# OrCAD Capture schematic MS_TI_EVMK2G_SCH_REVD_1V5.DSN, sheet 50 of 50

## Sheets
50 49. DC IN, 5V & DDR POWER GEN: size C; title: DDR3L POWER
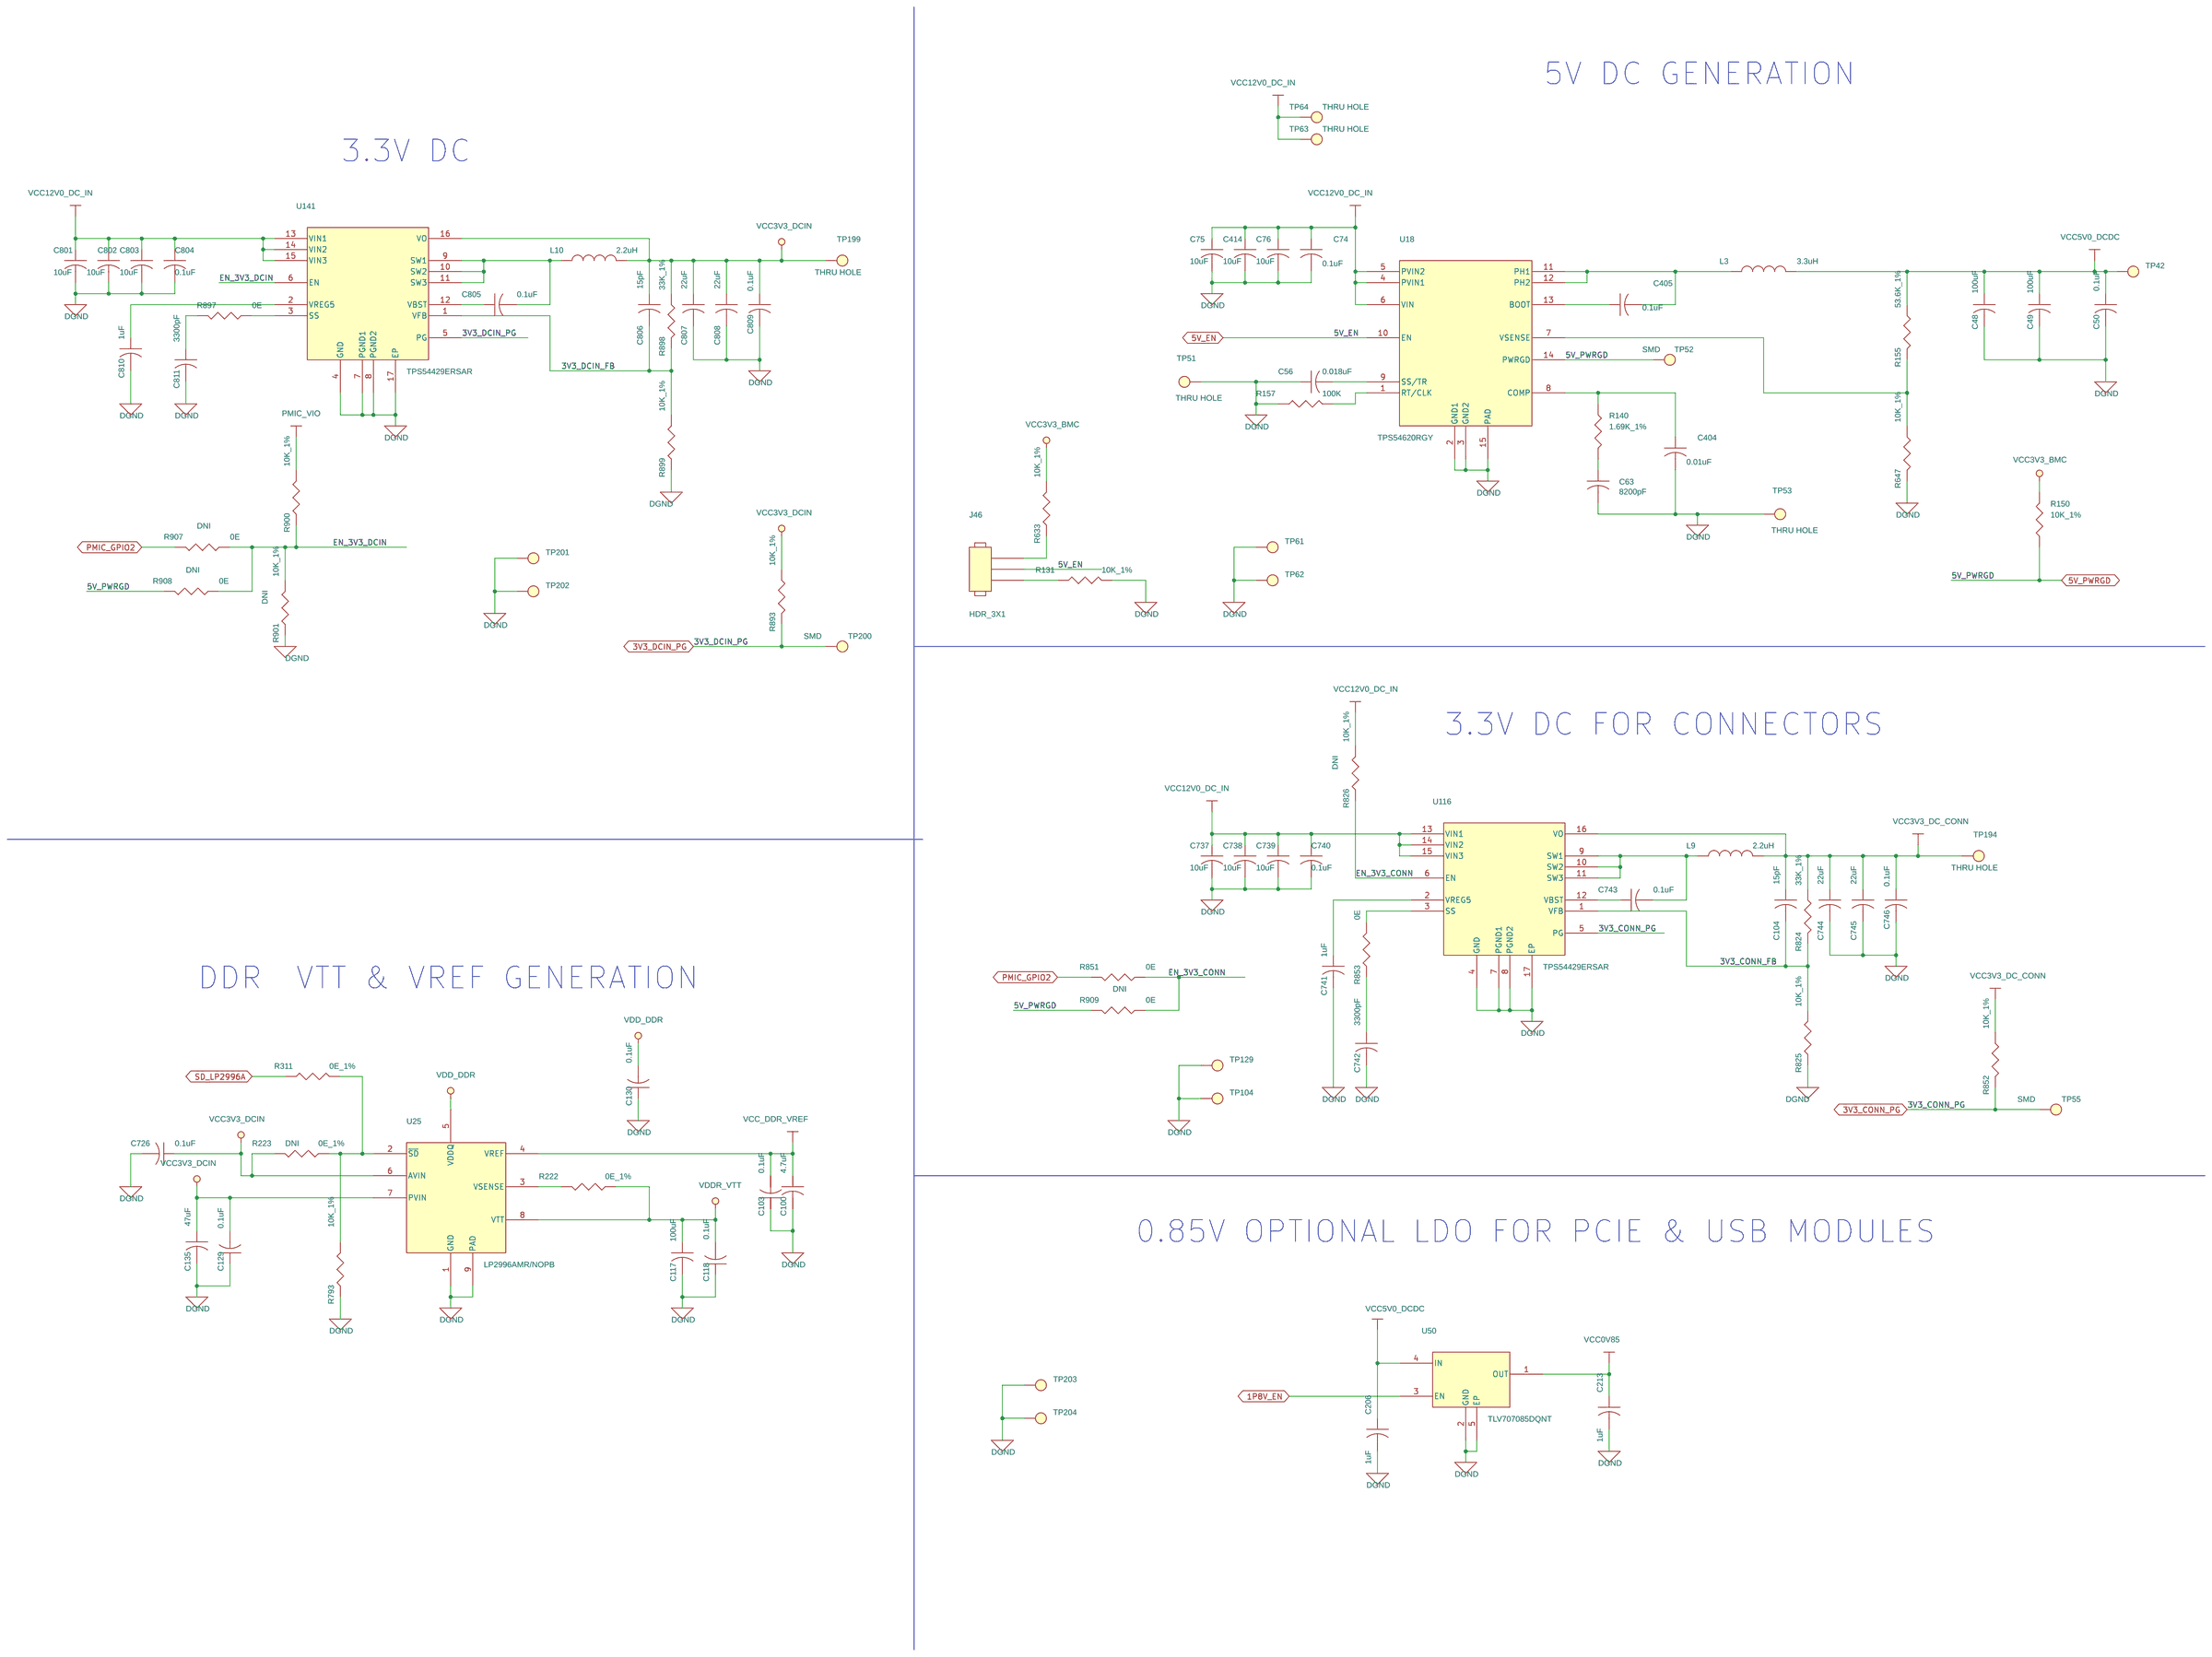
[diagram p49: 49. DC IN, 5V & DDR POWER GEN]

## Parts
C48  100uF  [CAP1210]
C49  100uF  [CAP1210]
C50  0.1uF  [CAP0402]
C56  0.018uF  [CAP0402]
C63  8200pF  [CAP0402]
C74  0.1uF  [CAP0402]
C75  10uF  [CAP1210]
C76  10uF  [CAP1210]
C100  4.7uF  [CAP0603]
C103  0.1uF  [CAP0402]
C104  15pF  [CAP0402]
C117  100uF  [CAP1210]
C118  0.1uF  [CAP0402]
C129  0.1uF  [CAP0402]
C130  0.1uF  [CAP0402]
C135  47uF  [CAP1206]
C206  1uF  [CAP0402]
C213  1uF  [CAP0402]
C404  0.01uF  [CAP0402]
C405  0.1uF  [CAP0402]
C414  10uF  [CAP1210]
C726  0.1uF  [CAP0402]
C737  10uF  [CAP1210]
C738  10uF  [CAP1210]
C739  10uF  [CAP1210]
C740  0.1uF  [CAP0402]
C741  1uF  [CAP0402]
C742  3300pF  [CAP0805]
C743  0.1uF  [CAP0402]
C744  22uF  [CAP1210]
C745  22uF  [CAP1210]
C746  0.1uF  [CAP0402]
C801  10uF  [CAP1210]
C802  10uF  [CAP1210]
C803  10uF  [CAP1210]
C804  0.1uF  [CAP0402]
C805  0.1uF  [CAP0402]
C806  15pF  [CAP0402]
C807  22uF  [CAP1210]
C808  22uF  [CAP1210]
C809  0.1uF  [CAP0402]
C810  1uF  [CAP0402]
C811  3300pF  [CAP0805]
J46  HDR_3X1  [HDR_3X1_100_S_T]
L3  3.3uH  [IND_PCMB104T_455X405_SMD]
L9  2.2uH  [IND_B82476A_510X370_SMD]
L10  2.2uH  [IND_B82476A_510X370_SMD]
R131  10K_1%  [RES0402]
R140  1.69K_1%  [RES0402]
R150  10K_1%  [RES0402]
R155  53.6K_1%  [RES0603]
R157  100K  [RES0402]
R222  0E_1%  [RES0402]
R223  0E_1%  [RES0402]
R311  0E_1%  [RES0402]
R633  10K_1%  [RES0402]
R647  10K_1%  [RES0402]
R793  10K_1%  [RES0402]
R824  33K_1%  [RES0603]
R825  10K_1%  [RES0402]
R826  10K_1%  [RES0402]
R851  0E  [RES0402]
R852  10K_1%  [RES0402]
R853  0E  [RES0402]
R893  10K_1%  [RES0402]
R897  0E  [RES0402]
R898  33K_1%  [RES0603]
R899  10K_1%  [RES0402]
R900  10K_1%  [RES0402]
R901  10K_1%  [RES0402]
R907  0E  [RES0402]
R908  0E  [RES0402]
R909  0E  [RES0402]
TP42  THRU HOLE  [TP_40X65]
TP51  THRU HOLE  [TP_40X65]
TP52  SMD  [TP40_SMD]
TP53  THRU HOLE  [TP_40X65]
TP55  SMD  [TP40_SMD]
TP61  THRU HOLE  [TP_40X65]
TP62  THRU HOLE  [TP_40X65]
TP63  THRU HOLE  [TP_40X65]
TP64  THRU HOLE  [TP_40X65]
TP104  THRU HOLE  [TP_40X65]
TP129  THRU HOLE  [TP_40X65]
TP194  THRU HOLE  [TP_40X65]
TP199  THRU HOLE  [TP_40X65]
TP200  SMD  [TP40_SMD]
TP201  THRU HOLE  [TP_40X65]
TP202  THRU HOLE  [TP_40X65]
TP203  THRU HOLE  [TP_40X65]
TP204  THRU HOLE  [TP_40X65]
U18  TPS54620RGY  [QFN14_19-68_145X145]
U25  LP2996AMR/NOPB  [ESOIC8]
U50  TLV707085DQNT  [DQN_25-59_40X40]
U116  TPS54429ERSAR  [QFN16_25-59_160X160]
U141  TPS54429ERSAR  [QFN16_25-59_160X160]

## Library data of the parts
C48 C49 C117 = CAP: CAP CERAMIC 100uF10V 20% X5R 1210; Chkd/date: MAZHAR/161208; Crtd /date: MAZHAR/140505; Custom_Duty: 15%; Customs_HS_Code: 85322990; Distributor_name: DIGIKEY; Distributor_part_number: 587-1965-1-ND; Height: 2.10MM; Mfr_name: TAIYO YUDEN; Mfr_part_number: LMK325BJ107MM-T; Mistral Part No: 120009030172; Package: 1210; Part_type: CAPACITORS\CERAMIC; Project: SMART VIEW_NVR; Tolerance: 20%; Voltage: 10V; Datasheet: Y:\MIS_DATABASE\DATASHEETS\CAPACITORS\JMKSERIES.PDF
C50 C405 C743 C746 C805 C809 = CAP: CAP CERAMIC 0.1uF 16V 10% X7R 0402; Alternate_mfr_name_A: KEMET; Alternate_mfr_part_number_A: C0402C104K4RACT; Chkd/date: MAZHAR/281108; Crtd /date: MAZHAR/030907; Custom_Duty: 15%; Customs_HS_Code: 85322990; Distributor_name: DIGIKEY; Distributor_name_A: DIGIKEY; Distributor_part_number: 490-3261-1-ND; Distributor_part_number_A: 399-3521-1-ND; Height: 0.55MM; Mfr_name: MURATA; Mfr_part_number: GRM155R71C104KA88D; Mistral Part No: 120009030060-R; Package: 0402; Part_type: CAPACITORS\CERAMIC; Project: SMART VIEW_IP CAMERA; Tolerance: 10%; Voltage: 16V; Datasheet: Y:\MIS_DATABASE\DATASHEETS\CAPACITORS\GRM188SERIES.PDF
C56 = CAP: CAP CERAMIC 0.018uF 16V 10% X7R 0402; Alternate_mfr_name_A: AVX CORPORATION; Alternate_mfr_name_B: MURATA; Alternate_mfr_part_number_A: 0402YC183KAT2A; Alternate_mfr_part_number_B: GRM155R71C183KA01D; Chkd/date: NAVEED/241114; Crtd /date: MUDDU/080310; Custom_Duty: 15%; Customs_HS_Code: 85322990; Distributor_name: DIGIKEY; Distributor_name_A: DIGIKEY; Distributor_name_B: DIGIKEY; Distributor_part_number: PCC2137CT-ND; Distributor_part_number_A: 478-1117-1-ND; Distributor_part_number_B: 490-5417-1-ND; Height: 0.55MM; Mfr_name: PANASONIC-ECG; Mfr_part_number: ECJ-0EB1C183K; Mistral Part No: 120010030006-R; Package: 0402; Part_type: CAPACITORS\CERAMIC; Project: VME_DSP_SUITE; RoHS: RoHS; Temperature: -55°C+125°C; Tolerance: 10%; Voltage: 16V; Wattage: NA; Weight: NA; Datasheet: Y:\MIS_DATABASE\DATASHEETS\CAPACITORS\PAN-ECJ.PDF
C63 = CAP: CAP CERAMIC 8200pf 16V 10% X7R 0402; Chkd/date: MAZHAR/241208; Crtd /date: USMAN/080908; Custom_Duty: 15%; Customs_HS_Code: 85322990; Distributor_name: DIGIKEY; Distributor_part_number: 399-1037-1-ND; Height: 0.55MM; Mfr_name: KEMET; Mfr_part_number: C0402C822K4RACTU; Mistral Part No: 120009030502-R; Package: 0402; Part_type: CAPACITORS\CERAMIC; Project: MDI; RoHS: RoHS; Tolerance: 10%; Voltage: 16V; Datasheet: Y:\MIS_DATABASE\DATASHEETS\CAPACITORS\KEMET-C08.PDF
C74 C103 C118 C129 C130 C726 C740 C804 = CAP: CAP CERAMIC 0.1uF 50V 10% X7R 0402; Alternate_mfr_name_A: TDK CORPORATION; Alternate_mfr_part_number_A: CGA2B3X7R1H104K; Chkd/date: BAVISH/081111; Crtd /date: CHAITHANYA/051011; Custom_Duty: 15%; Customs_HS_Code: 85322990; Distributor_name: DIGIKEY; Distributor_name_A: DIGIKEY; Distributor_part_number: 445-5932-1-ND; Distributor_part_number_A: 445-6899-1-ND; Height: 0.55MM; Mfr_name: TDK CORPORATION; Mfr_part_number: C1005X7R1H104K; Mistral Part No: 120011100014-R; Package: 0402; Part_type: CAPACITORS\CERAMIC; Project: VP-4000-BASE-BOARD; RoHS: RoHS; Temperature: -55°C+125°C; Tolerance: 10%; Voltage: 50V; Wattage: NA; Weight: NA; Datasheet: Y:\MIS_DATABASE\DATASHEETS\CAPACITORS\C1005X7.PDF
C75 C76 C414 C737-C739 C801-C803 = CAP: CAP CERAMIC 10uF 25V 20% X7R 1210; Chkd/date: SHREESHAIL/200707; Crtd /date: MAZHAR/180707; Custom_Duty: 15%; Customs_HS_Code: 85322990; Distributor_name: DIGIKEY; Distributor_part_number: 445-1434-1-ND; Height: 2.80MM; Mfr_name: TDK CORPORATION; Mfr_part_number: C3225X7R1E106M; Mistral Part No: 120009030191-R; Package: 1210; Part_type: CAPACITORS\CERAMIC; Project: REVA-IBMS; RoHS: RoHS; Tolerance: 20%; Voltage: 25V; Datasheet: Y:\MIS_DATABASE\DATASHEETS\CAPACITORS\TDK_CAP.PDF
C100 = CAP: CAP CERAMIC 4.7uF 16V 10% X5R 0603; Chkd/date: VASANTHA/230714; Crtd /date: BAVISH/060511; Custom_Duty: 15%; Customs_HS_Code: 85322990; Distributor_name: DIGIKEY; Distributor_part_number: 587-2786-1-ND; Height: 0.90MM; Mfr_name: TAIYO YUDEN; Mfr_part_number: EMK107ABJ475KA-T; Mistral Part No: 120011050004-R; Package: 0603; Part_type: CAPACITORS\CERAMIC; Project: HMC; RoHS: RoHS; Temperature: -55°C+85°C; Tolerance: 10%; Voltage: 16V; Wattage: NA; Weight: NA; Datasheet: Y:\MIS_DATABASE\DATASHEETS\CAPACITORS\EMK107.PDF
C104 C806 = CAP: CAP CERAMIC 15pF 50V 5% NP0 0402; Alternate_mfr_name_A: AVX CORPORATION; Alternate_mfr_name_B: KEMET; Alternate_mfr_name_D: MURATA; Alternate_mfr_part_number_A: 04025A150JAT2A; Alternate_mfr_part_number_B: C0402C150J5GACTU; Alternate_mfr_part_number_D: GRM1555C1H150JZ01D; Chkd/date: SHREESHAIL/220506; Crtd /date: MAZHAR/150506; Custom_Duty: 15%; Customs_HS_Code: 85322990; Distributor_name: DIGIKEY; Distributor_name_A: DIGIKEY; Distributor_name_B: DIGIKEY; Distributor_name_D: DIGIKEY; Distributor_part_number: PCC150CQCT-ND; Distributor_part_number_A: 478-1072-1-ND; Distributor_part_number_B: 399-1014-1-ND; Distributor_part_number_D: 490-1280-1-ND; Height: 0.55MM; Mfr_name: PANASONIC-ECG; Mfr_part_number: ECJ-0EC1H150J; Mistral Part No: 120009030233-R; Package: 0402; Part_type: CAPACITORS\CERAMIC; Project: VOCERA; RoHS: RoHS; Tolerance: 5%; Voltage: 50V; Datasheet: Y:\MIS_DATABASE\DATASHEETS\CAPACITORS\ECJ.PDF
C135 = CAP: CAP CERAMIC 47uF 16V 20% X5R 1206; Chkd/date: JAGADEESWARAN.S/250414; Crtd /date: BAVISH/010611; Custom_Duty: 15%; Customs_HS_Code: 85322990; Distributor_name: DIGIKEY; Distributor_part_number: 445-6003-1-ND; Height: 1.80MM; Mfr_name: TDK CORPORATION; Mfr_part_number: C3216X5R1C476M; Mistral Part No: 120011060001-R; Package: 1206; Part_type: CAPACITORS\CERAMIC; Project: TE_MODULE; RoHS: RoHS; Temperature: -55°C+85°C; Tolerance: 20%; Voltage: 16V; Wattage: NA; Weight: NA; Datasheet: Y:\MIS_DATABASE\DATASHEETS\CAPACITORS\TDK-C3216.PDF
C206 C213 C741 C810 = CAP: CAP CERAMIC 1uF 10V 10% X5R 0402; Chkd/date: BALACHANDAR/160514; Crtd /date: SARANYA/060514; Custom_Duty: 15%; Customs_HS_Code: 85322990; Distributor_name: DIGIKEY; Distributor_part_number: 478-4596-1-ND; Height: 0.56MM; Mfr_name: AVX CORPORATION; Mfr_part_number: 0402ZD105KAT2A; Mistral Part No: 120014050010-R; Package: 0402; Part_type: CAPACITORS\CERAMIC; Project: AEGIS GP BETA2; RoHS: RoHS; Temperature: -55°C+85°C; Tolerance: 10%; Voltage: 10V; Wattage: NA; Weight: NA; Datasheet: Y:\MIS_DATABASE\DATASHEETS\CAPACITORS\AVX_MLC.PDF
C404 = CAP: CAP CERAMIC 0.01uF 16V 10% X7R 0402; Alternate_mfr_name_A: AVX CORPORATION; Alternate_mfr_name_B: KEMET; Alternate_mfr_name_D: TDK CORPORATION; Alternate_mfr_part_number_A: 0402YC103KAT2A; Alternate_mfr_part_number_B: C0402C103K4RACTU; Alternate_mfr_part_number_D: C1005X7R1C103K; Chkd/date: SHREESHAIL/180506; Crtd /date: MAZHAR/110506; Custom_Duty: 15%; Customs_HS_Code: 85322990; Distributor_name: DIGIKEY; Distributor_name_A: DIGIKEY; Distributor_name_B: DIGIKEY; Distributor_name_D: DIGIKEY; Distributor_part_number: PCC103BQCT-ND; Distributor_part_number_A: 478-1114-1-ND; Distributor_part_number_B: 399-1038-1-ND; Distributor_part_number_D: 445-1262-1-ND; Height: 0.55MM; Mfr_name: PANASONIC-ECG; Mfr_part_number: ECJ-0EB1C103K; Mistral Part No: 120009030032-R; Package: 0402; Part_type: CAPACITORS\CERAMIC; Project: VOCERA; RoHS: RoHS; Tolerance: 10%; Voltage: 16V; Datasheet: Y:\MIS_DATABASE\DATASHEETS\CAPACITORS\PAN-ECJ.PDF
C742 C811 = CAP: CAP CERAMIC 3300pF 50V 5% X7R 0805; Chkd/date: PRASHANTHA/191011; Crtd /date: CHAITHANYA/041011; Custom_Duty: 15%; Customs_HS_Code: 85322990; Distributor_name: MOUSER; Distributor_part_number: 81-GRM216R71H332JA01D; Height: 1.35MM; Mfr_name: MURATA; Mfr_part_number: GRM216R71H332JA01D; Mistral Part No: 120011100005-R; Package: 0805; Part_type: CAPACITORS\CERAMIC; Project: VP-4000-BASE-BOARD; RoHS: RoHS; Temperature: -55°C+125°C; Tolerance: 5%; Voltage: 50V; Wattage: NA; Weight: NA; Datasheet: Y:\MIS_DATABASE\DATASHEETS\CAPACITORS\GRM188SERIES.PDF
C744 C745 C807 C808 = CAP: CAP CERAMIC 22uF 25V 10% X7R 1210; Chkd/date: BAVISH/040311; Crtd /date: MAZHAR/190111; Custom_Duty: 15%; Customs_HS_Code: 85322990; Distributor_name: DIGIKEY; Distributor_part_number: 490-5313-1-ND; Height: 2.70MM; Mfr_name: MURATA; Mfr_part_number: GRM32ER71E226KE15L; Mistral Part No: 120011010016-R; Package: 1210; Part_type: CAPACITORS\CERAMIC; Project: ITS-PWR_CARD; RoHS: RoHS; Temperature: -55°C+125°C; Tolerance: 10%; Voltage: 25V; Wattage: NA; Weight: NA; Datasheet: Y:\MIS_DATABASE\DATASHEETS\CAPACITORS\GRM32,43,55.PDF
J46 = HEADER_3X1: CON HDR 3X1 2.54MM PITCH ST TH; Chkd/date: MAZHAR/100311; Crtd /date: BAVISH/160211; Custom_Duty: 24%; Customs_HS_Code: 85369090; Distributor_name: DIGIKEY; Distributor_part_number: A26545-ND; Height: 10.74MM; Mfr_name: TYCO ELECTRONICS; Mfr_part_number: 87224-3; Mistral Part No: 150011020004-R; Package: THRU-HOLE; Part_type: CONNECTOR\HEADERS; Project: OMAPL1_PEC20; RoHS: RoHS; Temperature: NA; Tolerance: NA; Voltage: NA; Wattage: NA; Weight: NA; Datasheet: Y:\MIS_DATABASE\DATASHEETS\CONNECTORS\87224.PDF
L3 = INDUCTOR: IND COIL 3.3uH 16A 20% SMD; Chkd/date: Ravi/041010; Crtd /date: MUDDU/190610; Custom_Duty: 24%; Customs_HS_Code: 85437099; Distributor_name: DIGIKEY; Distributor_part_number: 408-1338-1-ND; Height: 4.00MM; Mfr_name: SUSUMU; Mfr_part_number: PCMB104T-3R3MS; Mistral Part No: 130010060031-R; Package: SMD; Project: CENTAURUS; RoHS: RoHS; Temperature: -55°C+125°C; Tolerance: 20%; Weight: NA; Datasheet: Y:\MIS_DATABASE\DATASHEETS\DISCRETES\INDUCTORS\PCMB104T.PDF
L9 L10 = INDUCTOR: IND POWER 2.2uH 6.1A 20% SMD; Chkd/date: BAVISH/210311; Crtd /date: MAZHAR/140610; Custom_Duty: 24%; Customs_HS_Code: 85437099; Distributor_name: DIGIKEY; Distributor_part_number: 495-2687-1-ND; Height: 5.08MM; Mfr_name: EPCOS; Mfr_part_number: B82476A1222M; Mistral Part No: 130010060018-R; Package: SMD; Project: SHIVA; RoHS: RoHS; Temperature: NA; Tolerance: 20%; Voltage: NA; Wattage: NA; Weight: 2g; Datasheet: Y:\MIS_DATABASE\DATASHEETS\DISCRETES\INDUCTORS\B82476A1.PDF
R131 R150 R633 R647 R793 R825 R852 R893 R899 R900 = RESISTOR: RES 10K 1/16W 1% 0402; Alternate_mfr_name_A: AVX CORPORATION; Alternate_mfr_name_B: PANASONIC-ECG-ECG; Alternate_mfr_name_C: YAGEO AMERICA; Alternate_mfr_name_D: VISHAY; Alternate_mfr_part_number_A: CR05-103F-H; Alternate_mfr_part_number_B: ERJ-2RKF1002X; Alternate_mfr_part_number_C: 9C04021A1002FLHF3; Alternate_mfr_part_number_D: CRCW040210K0FKED; Chkd/date: SHREESHAIL/310506; Crtd /date: GEETHA/290506; Custom_Duty: 15%; Customs_HS_Code: 85332119; Distributor_name: DIGIKEY; Distributor_name_A: NA; Distributor_name_B: DIGIKEY; Distributor_name_C: DIGIKEY; Distributor_name_D: DIGIKEY; Distributor_part_number: 311-10.0KLRTR-ND; Distributor_part_number_A: NA; Distributor_part_number_B: P10.0KLCT-ND; Distributor_part_number_C: 311-10.0KLCT-ND; Distributor_part_number_D: 541-10.0KLCT-ND; Height: 0.40MM; Mfr_name: YAGEO AMERICA; Mfr_part_number: RC0402FR-0710KL; Mistral Part No: 110009030220-P; Package: 0402; Part_type: RESISTORS\FIXED; Project: VOCERA; RoHS: Pb-Free; Tolerance: 1%; Wattage: 1/16W; Datasheet: Y:\MIS_DATABASE\DATASHEETS\RESISTORS\YAGEO-RC0402.PDF
R140 = RESISTOR: RES 1.69K 1/16W 1% 0402; Alternate_mfr_name_A: AVX CORPORATION; Alternate_mfr_part_number_A: CR05-1691F-H; Chkd/date: SHREESHAIL/121205; Crtd /date: MAZHAR/180705; Custom_Duty: 15%; Customs_HS_Code: 85332119; Distributor_name: DIGIKEY; Distributor_name_A: NA; Distributor_part_number: P1.69KLCT-ND; Distributor_part_number_A: NA; Height: 0.40MM; Mfr_name: PANASONIC-ECG; Mfr_part_number: ERJ-2RKF1691X; Mistral Part No: 110009030133-R; Package: 0402; Part_type: RESISTORS\FIXED; Project: PMP-VIOMEDIA; RoHS: RoHS; Tolerance: 1%; Wattage: 1/16W; Datasheet: Y:\MIS_DATABASE\DATASHEETS\RESISTORS\PAN_ERJ.PDF
R155 = RESISTOR: RES 53.6K 1/10W 1% 0603; Alternate_mfr_name_C: YAGEO AMERICA; Alternate_mfr_part_number_C: 9C06031A5362FKHFT; Chkd/date: SHREESHAIL/220506; Crtd /date: GEETHA/190506; Custom_Duty: 15%; Customs_HS_Code: 85332119; Distributor_name: DIGIKEY; Distributor_name_C: DIGIKEY; Distributor_part_number: P53.6KHCT-ND; Distributor_part_number_C: 311-53.6KHCT-ND; Height: 0.55MM; Mfr_name: PANASONIC-ECG; Mfr_part_number: ERJ-3EKF5362V; Mistral Part No: 110009030974-R; Package: 0603; Part_type: RESISTORS\FIXED; Project: VOCERA; RoHS: RoHS; Tolerance: 1%; Wattage: 1/10W; Datasheet: Y:\MIS_DATABASE\DATASHEETS\RESISTORS\PAN_ERJ.PDF
R157 = RESISTOR: RES 100K 1/16W 5% 0402; Alternate_mfr_name_A: AVX CORPORATION; Alternate_mfr_part_number_A: CR05-104J-H; Chkd/date: SHREESHAIL/200406; Crtd /date: GEETHA/190406; Custom_Duty: 15%; Customs_HS_Code: 85332119; Distributor_name: DIGIKEY; Distributor_name_A: NA; Distributor_part_number: P100KJCT-ND; Distributor_part_number_A: NA; Height: 0.40MM; Mfr_name: PANASONIC-ECG; Mfr_part_number: ERJ-2GEJ104X; Mistral Part No: 110009030177-R; Package: 0402; Part_type: RESISTORS\FIXED; Project: RED EYE; RoHS: RoHS; Tolerance: 5%; Wattage: 1/16W; Datasheet: Y:\MIS_DATABASE\DATASHEETS\RESISTORS\ERJ12.PDF
R222 R311 = RESISTOR: RES 0E 1/16W 1% 0402; Chkd/date: MAZHAR/220709; Crtd /date: USMAN/270109; Custom_Duty: 15%; Customs_HS_Code: 85332119; Distributor_name: NA; Distributor_part_number: NA; Height: 0.40MM; Mfr_name: YAGEO AMERICA; Mfr_part_number: RC0402FR-070RL; Mistral Part No: 110009030085-P; Package: 0402; Part_type: RESISTORS\FIXED; Project: OMAP_EVM; RoHS: Pb-Free; Tolerance: 1%; Wattage: 1/16W; Datasheet: Y:\MIS_DATABASE\DATASHEETS\RESISTORS\CRCW0603.PDF
R223 = RESISTOR: RES 0E 1/16W 1% 0402; Chkd/date: MAZHAR/220709; Crtd /date: USMAN/270109; Custom_Duty: 15%; Customs_HS_Code: 85332119; Distributor_name: NA; Distributor_part_number: NA; Height: 0.40MM; Loading: DNI; Mfr_name: YAGEO AMERICA; Mfr_part_number: RC0402FR-070RL; Mistral Part No: 110009030085-P; Package: 0402; Part_type: RESISTORS\FIXED; Project: OMAP_EVM; RoHS: Pb-Free; Tolerance: 1%; Wattage: 1/16W; Datasheet: Y:\MIS_DATABASE\DATASHEETS\RESISTORS\CRCW0603.PDF
R824 R898 = RESISTOR: RES 33K 1/10W 1% 0603; Chkd/date: SUHAS/240910; Crtd /date: MUDDU/210610; Custom_Duty: 15%; Customs_HS_Code: 85332119; Distributor_name: DIGIKEY; Distributor_part_number: 541-33.0KHCT-ND; Height: 0.55MM; Mfr_name: VISHAY; Mfr_part_number: CRCW060333K0FKEA; Mistral Part No: 110010060023-P; Package: 0603; Part_type: RESISTORS\FIXED; Project: NPOL_CONTROLLERCARD; RoHS: Pb-Free; Temperature: -55°C+155°C; Tolerance: 1%; Voltage: 75V; Wattage: 1/10W; Weight: 2g/1000pcs; Datasheet: Y:\MIS_DATABASE\DATASHEETS\RESISTORS\CRCW.PDF
R826 R901 = RESISTOR: RES 10K 1/16W 1% 0402; Alternate_mfr_name_A: AVX CORPORATION; Alternate_mfr_name_B: PANASONIC-ECG-ECG; Alternate_mfr_name_C: YAGEO AMERICA; Alternate_mfr_name_D: VISHAY; Alternate_mfr_part_number_A: CR05-103F-H; Alternate_mfr_part_number_B: ERJ-2RKF1002X; Alternate_mfr_part_number_C: 9C04021A1002FLHF3; Alternate_mfr_part_number_D: CRCW040210K0FKED; Chkd/date: SHREESHAIL/310506; Crtd /date: GEETHA/290506; Custom_Duty: 15%; Customs_HS_Code: 85332119; Distributor_name: DIGIKEY; Distributor_name_A: NA; Distributor_name_B: DIGIKEY; Distributor_name_C: DIGIKEY; Distributor_name_D: DIGIKEY; Distributor_part_number: 311-10.0KLRTR-ND; Distributor_part_number_A: NA; Distributor_part_number_B: P10.0KLCT-ND; Distributor_part_number_C: 311-10.0KLCT-ND; Distributor_part_number_D: 541-10.0KLCT-ND; Height: 0.40MM; Loading: DNI; Mfr_name: YAGEO AMERICA; Mfr_part_number: RC0402FR-0710KL; Mistral Part No: 110009030220-P; Package: 0402; Part_type: RESISTORS\FIXED; Project: VOCERA; RoHS: Pb-Free; Tolerance: 1%; Wattage: 1/16W; Datasheet: Y:\MIS_DATABASE\DATASHEETS\RESISTORS\YAGEO-RC0402.PDF
R851 R853 R897 = RESISTOR: RES 0E 1/10W 5% 0402; Chkd/date: NAVEED/241114; Crtd /date: NAVEED/201014; Custom_Duty: 15%; Customs_HS_Code: 85332119; Distributor_name: DIGIKEY; Distributor_part_number: P0.0JCT-ND; Height: 0.40MM; Mfr_name: PANASONIC-ECG; Mfr_part_number: ERJ-2GE0R00X; Mistral Part No: 110014100008-R; Package: 0402; Part_type: RESISTORS\FIXED; Project: AEGIS POM; RoHS: RoHS; Tolerance: 5%; Wattage: 1/10W; Datasheet: Y:\MIS_DATABASE\DATASHEETS\RESISTORS\ERJ12.PDF
R907-R909 = RESISTOR: RES 0E 1/10W 5% 0402; Chkd/date: NAVEED/241114; Crtd /date: NAVEED/201014; Custom_Duty: 15%; Customs_HS_Code: 85332119; Distributor_name: DIGIKEY; Distributor_part_number: P0.0JCT-ND; Height: 0.40MM; Loading: DNI; Mfr_name: PANASONIC-ECG; Mfr_part_number: ERJ-2GE0R00X; Mistral Part No: 110014100008-R; Package: 0402; Part_type: RESISTORS\FIXED; Project: AEGIS POM; RoHS: RoHS; Tolerance: 5%; Wattage: 1/10W; Datasheet: Y:\MIS_DATABASE\DATASHEETS\RESISTORS\ERJ12.PDF
TP42 TP51 TP53 TP61-TP64 TP104 TP129 TP194 TP199 TP201-TP204 = TESTPOINT: TESTPOINT 1.0MM DRILL PTH; Chkd/date: MAZHAR/271211; Crtd /date: SHREESHAIL/041005; Distributor_name: NA; Distributor_part_number: NA; Height: NA; Mfr_name: LOCAL; Mistral Part No: 130009030938; Package: THRU-HOLE; Part_type: MISC\TESTPOINT; Project: HSE; Datasheet: NA
TP52 TP55 TP200 = TESTPOINT: TESTPOINT 40 SMD; Chkd/date: MAZHAR/190505; Crtd /date: MAZHAR/190505; Distributor_name: NA; Distributor_part_number: NA; Height: NA; Mfr_name: LOCAL; Mistral Part No: 130009030933; Part_type: MISC\TESTPOINT; Project: RAINIER-3
U18 = TPS54620_QFN14: IC BUCK SYNCHRONOUS STEP DOWN SWIFT CONVERTER QFN14; Chkd/date: MAZHAR/220310; Crtd /date: MUDDU/020310; Custom_Duty: 15%; Customs_HS_Code: 85423100; Distributor_name: DIGIKEY; Distributor_part_number: 296-24554-1-ND; Height: 1.00MM; Mfr_name: TEXAS INSTRUMENTS; Mistral Part No: 142010020026; Package: QFN14; Part_type: ICS\POWER\DC-DC CONVERTER; Project: VME_DSP_SUITE; Temperature: -40°C+150°C; Weight: NA; Datasheet: Y:\MIS_DATABASE\DATASHEETS\ICS\POWER\TPS54620.PDF
U25 = LP2996MR_PSOP8: IC DDR TERMINATION REGULATOR PSOP8; Chkd/date: NAVEED/060115; Crtd /date: VASANTHA/171114; Custom_Duty: 15%; Customs_HS_Code: 85423100; Distributor_name: DIGIKEY; Distributor_part_number: 296-37966-5-ND; Height: 1.68MM; Mfr_name: TEXAS INSTRUMENTS; Mistral Part No: 142014110008-R; Package: PSOP8; Part_type: ICS\POWER\VOLTAGE REGULATOR; Project: GALILEO_EVM; RoHS: RoHS; Temperature: -0°C+125°C; Tolerance: NA; Voltage: NA; Wattage: NA; Weight: NA; Datasheet: Y:\MIS_DATABASE\DATASHEETS\MISC\REGULATORS\LP2996AM.PDF
U50 = TLV707085DQNT_SMD: IC LDO LINEAR REGULATOR 200mA 2V SMD; Chkd/date: NAVEED/070115; Crtd /date: JEBRAN/141114; Custom_Duty: 15%; Customs_HS_Code: 85423100; Distributor_name: DIGIKEY; Distributor_part_number: TLV707085DQNT-ND; Height: 0.40MM; Mfr_name: TEXAS INSTRUMENTS; Mistral Part No: 142014110007-R; Package: SMD; Part_type: ICS\POWER\VOLTAGE REGULATOR; Project: GALILEO EVM; RoHS: RoHS; Temperature: -40°C+125°C; Tolerance: NA; Voltage: 2.0V; Wattage: NA; Weight: NA; Datasheet: Y:\MIS_DATABASE\DATASHEETS\MISC\REGULATORS\TLV707-SER.PDF
U116 U141 = TPS54429ERSAR_QFN16: IC SYNCHRONOUS STEP DOWN SWIFT 4.5A QFN16; Chkd/date: NAVEED/070115; Crtd /date: VASANTHA/171214; Custom_Duty: 15%; Customs_HS_Code: 85423100; Distributor_name: DIGIKEY; Distributor_part_number: 296-28909-1-ND; Height: 1.00MM; Mfr_name: TEXAS INSTRUMENTS; Mistral Part No: 142014120016-R; Package: QFN16; Part_type: ICS\POWER\CONVERTER; Project: GALILEO_EVM; RoHS: RoHS; Temperature: -20°C+85°C; Tolerance: NA; Voltage: NA; Wattage: NA; Weight: NA; Datasheet: Y:\MIS_DATABASE\DATASHEETS\ICS\POWER\TPS54429E.PDF

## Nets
3V3_CONN_FB: C104.2 R824.2 R825.2 U116.1(VFB)
3V3_CONN_PG: R852.2 TP55.1(TP) U116.5(PG) ; also on sheet 45
3V3_DCIN_FB: C806.2 R898.2 R899.2 U141.1(VFB)
3V3_DCIN_PG: R893.2 TP200.1(TP) U141.5(PG) ; also on sheet 45
5V_EN: J46.2 U18.10(EN) ; also on sheet 46
5V_PWRGD: R150.1 R908.2 R909.2 TP52.1(TP) U18.14(PWRGD) ; also on sheet 45
DGND: C48.2 C49.2 C50.2 C56.1 C63.2 C74.2 C75.2 C76.2 C100.2 C103.1 C117.2 C118.1 C129.1 C130.1 C135.2 C206.2 C213.2 C404.2 C414.2 C726.2 C737.2 C738.2 C739.2 C740.2 C741.2 C742.2 C744.2 C745.2 C746.2 C801.2 C802.2 C803.2 C804.2 C807.2 C808.2 C809.2 C810.2 C811.2 R131.1 R157.1 R647.2 R793.1 R825.1 R899.1 R901.1 TP51.1(TP) TP53.1(TP) TP61.1(TP) TP62.1(TP) TP104.1(TP) TP129.1(TP) TP201.1(TP) TP202.1(TP) TP203.1(TP) TP204.1(TP) U18.2(GND1) U18.3(GND2) U18.15(PAD) U25.1(GND) U25.9(PAD) U50.2(GND) U50.5(EP) U116.4(GND) U116.7(PGND1) U116.8(PGND2) U116.17(EP) U141.4(GND) U141.7(PGND1) U141.8(PGND2) U141.17(EP) ; also on sheet 1 11 12 13 14 15 16 17 18 19 20 21 22 23 24 25 26 27 28 29 30 31 32 33 34 35 36 37 38 39 40 41 42 43 44 45 46 47 48 49
VCC0V85: C213.1 U50.1(OUT) ; also on sheet 13
VCC3V3_BMC: R150.2 R633.2 ; also on sheet 13 28 29 37 38 45 46 47
VCC3V3_DC_CONN: C104.1 C744.1 C745.1 C746.1 L9.2 R824.1 R852.1 TP194.1(TP) U116.16(VO) ; also on sheet 26 32
VCC3V3_DCIN: C129.2 C135.1 C726.1 C806.1 C807.1 C808.1 C809.1 L10.2 R223.2 R893.1 R898.1 TP199.1(TP) U25.6(AVIN) U25.7(PVIN) U141.16(VO) ; also on sheet 11 17 18 19 20 21 22 23 24 25 26 27 28 29 30 31 32 33 34 35 36 37 38 43 44 45 46 47 48
VCC5V0_DCDC: C48.1 C49.1 C50.1 C206.1 L3.2 R155.1 TP42.1(TP) U50.4(IN) ; also on sheet 21 22 27 30 44 46 48 49
VCC12V0_DC_IN: C74.1 C75.1 C76.1 C414.1 C737.1 C738.1 C739.1 C740.1 C801.1 C802.1 C803.1 C804.1 R826.2 TP63.1(TP) TP64.1(TP) U18.4(PVIN1) U18.5(PVIN2) U18.6(VIN) U116.13(VIN1) U116.14(VIN2) U116.15(VIN3) U141.13(VIN1) U141.14(VIN2) U141.15(VIN3) ; also on sheet 1 26 31 33 34 47 48
VCC_DDR_VREF: C100.1 C103.2 U25.4(VREF) ; also on sheet 14 15 16
VDDR_VTT: C117.1 C118.2 R222.1 U25.8(VTT) ; also on sheet 16
1P8V_EN: U50.3(EN) ; also on sheet 49
EN_3V3_CONN: R826.1 R851.1 R909.1 U116.6(EN)
EN_3V3_DCIN: R900.1 R901.2 R907.1 R908.1 U141.6(EN)
PMIC_GPIO2: R851.2 R907.2 ; also on sheet 49
PMIC_VDD2: C130.2 U25.5(VDDQ) ; also on sheet 15 16 48
PMIC_VIO: R900.2 ; also on sheet 48 49
SD_LP2996A: R311.1 ; also on sheet 12
N19631369: R155.2 R647.1 U18.7(VSENSE)
N19631412: C405.2 L3.1 U18.11(PH1) U18.12(PH2)
N19631425: C56.2 U18.9(SS/TR)
N19631427: C404.1 R140.1 U18.8(COMP)
N19631452: C405.1 U18.13(BOOT)
N19631454: C63.1 R140.2
N19631468: R157.2 U18.1(RT/CLK)
N19631560: J46.3 R131.2
N21319043: R222.2 U25.3(VSENSE)
N21320308: R223.1 R311.2 R793.2 U25.2(~{SD})
N22822538: C742.1 R853.1
N23623251: C743.2 L9.1 U116.9(SW1) U116.10(SW2) U116.11(SW3)
N23623286: C743.1 U116.12(VBST)
N23623990: C741.1 U116.2(VREG5)
N23625135: R853.2 U116.3(SS)
N25716335: J46.1 R633.1
N26130196: C805.2 L10.1 U141.9(SW1) U141.10(SW2) U141.11(SW3)
N26130204: C805.1 U141.12(VBST)
N26130308: C810.1 U141.2(VREG5)
N26134731: R897.1 U141.3(SS)
N26134738: C811.1 R897.2

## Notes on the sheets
sheet 50
- 5V DC GENERATION
- 3.3V DC
- 3.3V DC FOR CONNECTORS
- DDR  VTT & VREF GENERATION
- 0.85V OPTIONAL LDO FOR PCIE & USB MODULES
